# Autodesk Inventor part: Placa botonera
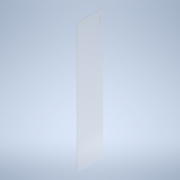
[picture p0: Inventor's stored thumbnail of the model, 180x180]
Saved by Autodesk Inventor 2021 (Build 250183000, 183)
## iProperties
Created: 2021-02
Part Number: Placa botonera
Material: Plástico PET
Document SubType Name: Modeling
Designer: ATOUZA
Density: 1.541 g/cm^3
Appearance: Policarbonato - Claro
Author: ATOUZA
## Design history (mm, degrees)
sketch "Boceto1"
  geometry: L1 (121.417, 308.504)-(1.417, 308.504); L2 (1.417, 308.504)-(1.417, -291.496); L3 (1.417, -291.496)-(121.417, -291.496); L4 (121.417, -291.496)-(121.417, 308.504); 1 further point
  constraints: 8 end point, 2 parallel, 1 horizontal, 1 perpendicular
  dimensions: "d0" = 600 distance of L3.end L1.start; "d1" = 120 distance of L1.start L1.end
extrude "Extrusión1" new body sketch "Boceto1" distance "d2" = 3; taper "d3" = 0 deg
sketch "Boceto2"
  geometry: L1 (-291.06, 111.142)-(-237.665, 111.142); L2 (-237.665, 111.142)-(-237.665, 94.892); L3 (-237.665, 94.892)-(-291.06, 94.892); L4 (-291.06, 94.892)-(-291.06, 111.142); 1 further point
  constraints: 2 other
feature "Repujado1" sketch "Boceto2" dims "d4" = 1, "d5" = 0
node "Sólido1"
